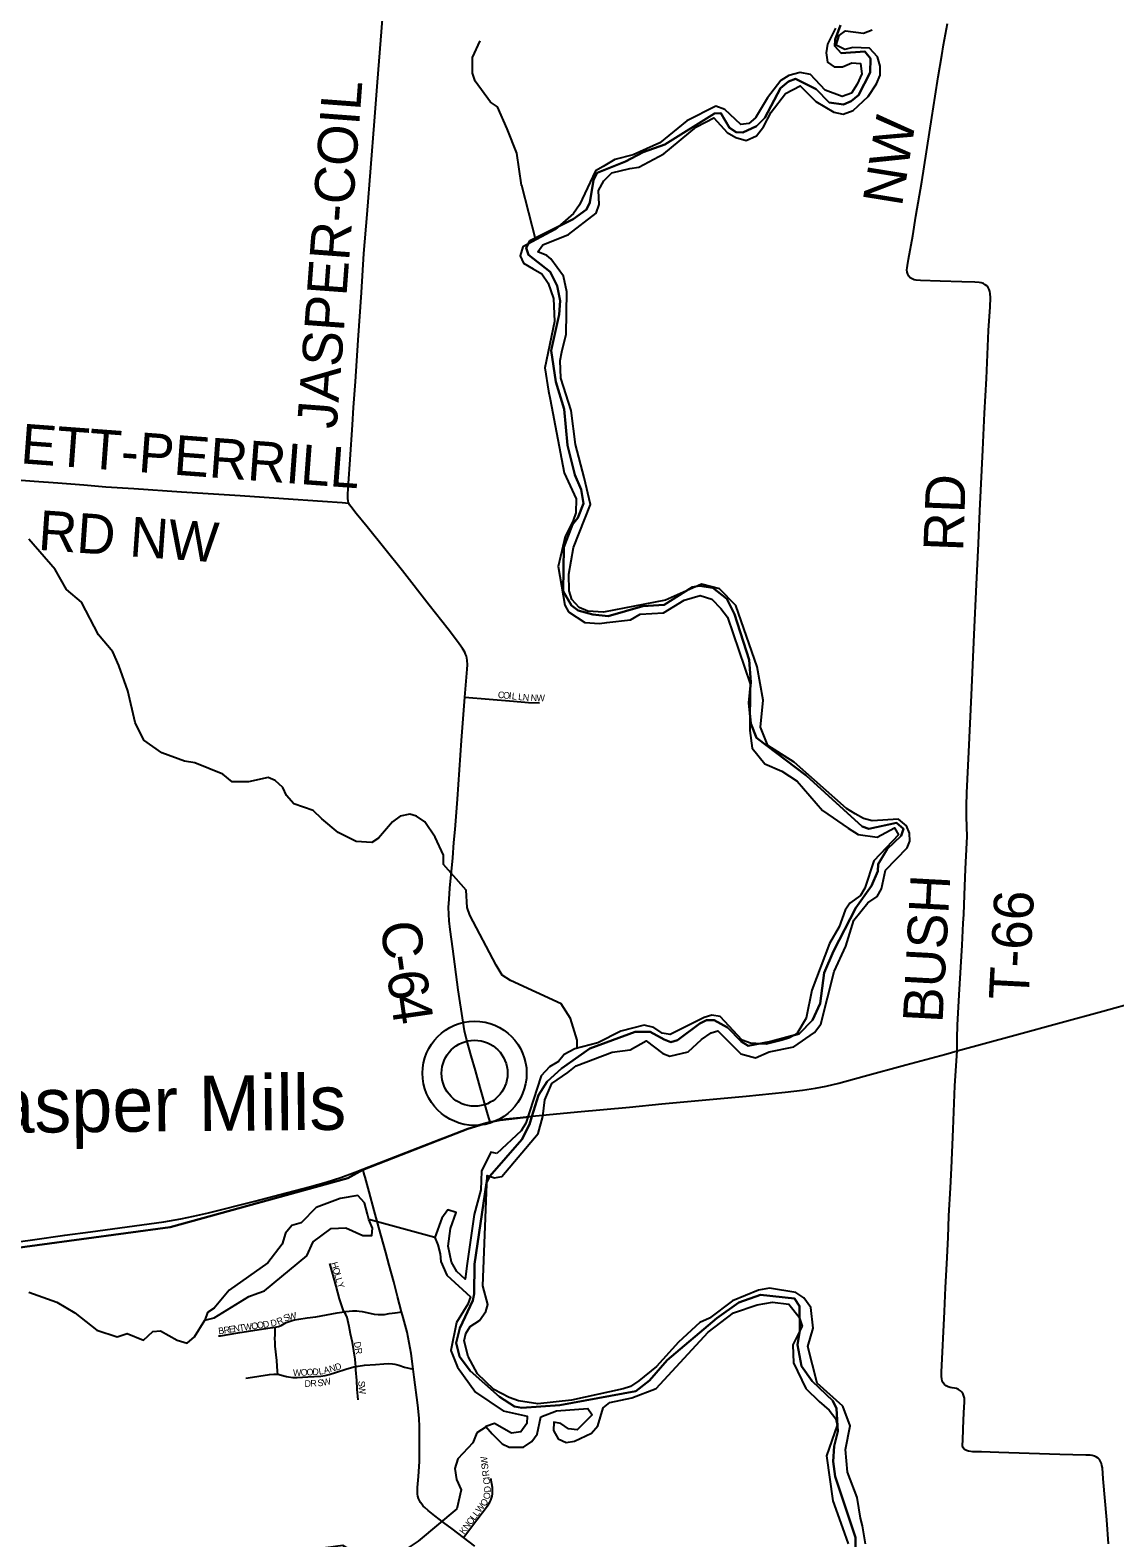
# Model space of a CAD drawing. Extents: x -51392 to 1635000, y 156707 to 696232.
# Drawn here: x 112561 to 120749, y 476810 to 488186 of the extents above; entities that cross this region are included whole.
import ezdxf

# ---------------------------------------------------------------- set-up
doc = ezdxf.new("R2010")
doc.units = 0
for name, color, linetype in [('GM_X_County_Road', 7, 'Continuous'), ('GM_X_County_Road_Text', 7, 'Continuous'), ('GM_X_Minor_Lake', 7, 'Continuous'), ('GM_X_Minor_River', 7, 'Continuous'), ('GM_X_Township', 7, 'Continuous'), ('GM_X_Township_Road', 7, 'Continuous'), ('GM_X_Township_Road_Text', 7, 'Continuous'), ('GM_X_Township_Subdivision', 7, 'Continuous'), ('GM_X_Township_Subdivision_Text', 7, 'Continuous'), ('GM_X_Unincorporated', 7, 'Continuous'), ('GM_X_Unincorporated_Text', 7, 'Continuous'), ('GM_X_US_Route', 7, 'Continuous')]:
    doc.layers.add(name, color=color, linetype=linetype)

msp = doc.modelspace()

# ---------------------------------------------------------------- linework, layer by layer
at = {"layer": 'GM_X_County_Road'}
for points in [[(114966, 484617), (114965, 484619), (114961, 484635), (114959, 484651), (114958, 484684), (114964, 484766), (114977, 484946), (114994, 485208), (115003, 485339), (115016, 485535), (115037, 485846), (115061, 486207), (115081, 486501), (115105, 486796), (115161, 487499), (115184, 487794), (115221, 488268)], [(112282, 484808), (112395, 484798), (112591, 484783), (112771, 484770), (112967, 484754), (113131, 484740), (113344, 484727), (113704, 484703), (114146, 484674), (114474, 484652), (114768, 484633), (114916, 484621), (114966, 484617)], [(115842, 483154), (115860, 483365), (115862, 483398), (115861, 483431), (115858, 483447), (115854, 483463), (115848, 483478), (115841, 483493), (115824, 483521), (115786, 483574), (115716, 483666), (115574, 483846), (115372, 484105), (115105, 484438), (115023, 484540), (114981, 484591), (114971, 484604), (114966, 484617)], [(116033, 479948), (116024, 479979), (116011, 480021), (115958, 480209), (115923, 480335), (115891, 480446), (115856, 480573), (115840, 480636), (115829, 480701), (115793, 480945), (115751, 481254), (115731, 481401), (115724, 481466), (115721, 481515), (115720, 481565), (115723, 481630), (115730, 481712), (115751, 481941), (115760, 482056), (115768, 482154), (115786, 482383), (115818, 482826), (115842, 483154)], [(115365, 478516), (115334, 478630), (115305, 478741), (115270, 478867), (115245, 478962), (115194, 479152), (115159, 479279), (115120, 479421), (115089, 479531), (115084, 479547), (115073, 479592)], [(115452, 478083), (115436, 478200), (115423, 478281), (115406, 478361), (115377, 478472), (115365, 478516)], [(115833, 476813), (115747, 476877), (115682, 476927), (115617, 476976), (115565, 477017), (115540, 477039), (115528, 477050), (115517, 477063), (115507, 477077), (115499, 477091), (115492, 477107), (115488, 477124), (115485, 477140), (115485, 477157), (115486, 477190), (115493, 477272), (115499, 477386), (115501, 477452), (115500, 477648), (115497, 477713), (115488, 477811), (115460, 478022), (115452, 478083)], [(115917, 476746), (115833, 476813)]]:
    msp.add_lwpolyline(points, dxfattribs=at)
at = {"layer": 'GM_X_Minor_Lake'}
for points in [[(115107, 479251), (115085, 479337), (115035, 479392), (114902, 479371), (114719, 479302), (114606, 479188), (114537, 479167), (114489, 479109), (114464, 479025), (114355, 478885), (114062, 478679), (113949, 478542), (113899, 478510), (113880, 478452), (113951, 478469), (114211, 478630), (114279, 478657), (114331, 478673), (114650, 478939), (114697, 479043), (114834, 479143), (114943, 479148), (115073, 479091), (115139, 479092), (115145, 479146), (115118, 479213)], [(115118, 479213), (115107, 479251)]]:
    msp.add_lwpolyline(points, dxfattribs=at)
at = {"layer": 'GM_X_Minor_River'}
for points in [[(118641, 488201), (118580, 488081), (118569, 488015), (118579, 487943), (118631, 487910), (118693, 487908), (118764, 487939), (118830, 487933), (118839, 487857), (118805, 487779), (118760, 487711), (118690, 487685), (118563, 487732), (118452, 487850), (118374, 487866), (118287, 487843), (118227, 487807), (118126, 487676), (118036, 487524), (117986, 487482), (117927, 487475), (117804, 487586), (117738, 487612), (117518, 487502), (117314, 487335), (117113, 487244), (116974, 487209), (116886, 487157), (116829, 487124), (116709, 486868), (116662, 486802), (116525, 486681), (116281, 486552), (116259, 486482), (116285, 486428), (116357, 486384), (116423, 486347), (116472, 486276), (116512, 486160), (116520, 485987), (116446, 485639), (116475, 485463), (116486, 485402), (116593, 484846), (116682, 484649), (116681, 484543), (116659, 484485), (116600, 484365), (116548, 484139), (116598, 483848), (116624, 483796), (116748, 483717), (116858, 483708), (116915, 483717), (117093, 483736), (117166, 483780), (117343, 483790), (117498, 483884), (117620, 483921), (117706, 483892), (117774, 483821), (117826, 483757), (117997, 483254), (117993, 482902), (118012, 482769), (118106, 482650), (118236, 482595), (118352, 482520), (118541, 482298), (118736, 482165), (118812, 482118), (118955, 482097), (119086, 482166), (119115, 482114), (118931, 481919), (118862, 481711), (118829, 481657), (118749, 481599), (118714, 481547)], [(117089, 487141), (117157, 487151), (117344, 487252), (117590, 487455), (117723, 487524), (117823, 487413), (117887, 487375), (117967, 487354), (118043, 487389), (118098, 487457), (118155, 487567), (118262, 487707), (118373, 487766), (118491, 487647), (118629, 487568), (118697, 487551), (118775, 487579), (118886, 487686), (118951, 487780), (118978, 487846), (118978, 487914), (118957, 487984), (118897, 488051), (118772, 488054), (118710, 488040), (118646, 488073), (118667, 488145), (118717, 488180), (118851, 488163), (118916, 488187)], [(116270, 487013), (116269, 487016), (116234, 487258), (116163, 487441), (116088, 487606), (116036, 487643), (115919, 487800), (115901, 487860), (115900, 487979), (115957, 488106)], [(116462, 486485), (116394, 486514), (116430, 486567), (116625, 486644), (116833, 486805), (116856, 486869), (116852, 486975), (116891, 487049), (116952, 487109), (117089, 487141)], [(116269, 487016), (116376, 486604)], [(118695, 477803), (118503, 477977), (118431, 478254), (118472, 478392), (118453, 478547), (118401, 478621), (118341, 478662), (118141, 478693), (118059, 478680), (117863, 478599), (117688, 478468), (117617, 478435), (117456, 478287), (117290, 478102), (117157, 477995), (117094, 477951), (117038, 477934), (116648, 477848), (116393, 477822), (116247, 477843), (116178, 477868), (116060, 477929), (115937, 478048), (115867, 478179), (115838, 478297), (115849, 478351), (115883, 478405), (115952, 478449), (116002, 478519), (116015, 478571), (115979, 478711), (116011, 479545), (116065, 479526), (116121, 479536), (116395, 479861), (116432, 479989), (116447, 480115), (116500, 480237), (116621, 480320), (116683, 480372), (116955, 480474), (117091, 480493), (117210, 480560), (117338, 480465), (117390, 480445), (117529, 480478), (117630, 480569), (117702, 480621), (117753, 480636), (117926, 480461), (118036, 480432), (118139, 480477), (118326, 480516), (118481, 480623), (118530, 480687), (118631, 481083), (118718, 481275), (118780, 481471), (118885, 481602), (118956, 481650), (118988, 481708), (119017, 481848), (119181, 482015), (119201, 482067), (119200, 482127), (119176, 482181), (119116, 482232), (118917, 482219), (118853, 482238), (118789, 482273), (118723, 482313), (118328, 482663), (118129, 482788), (118075, 482927), (118095, 483130), (118050, 483382), (117887, 483845), (117765, 483970), (117629, 484005), (117357, 483885), (116889, 483794), (116771, 483803), (116705, 483829), (116649, 483890), (116629, 483956), (116628, 484080), (116663, 484281), (116792, 484606), (116743, 484811), (116677, 485060), (116644, 485315), (116568, 485560), (116561, 485692), (116575, 485759), (116608, 485891), (116612, 486211), (116587, 486330), (116492, 486459), (116462, 486485)], [(116690, 480504), (116690, 480564), (116639, 480729), (116570, 480840), (116188, 481015), (116124, 481055), (116080, 481130), (115880, 481508), (115860, 481566), (115853, 481697), (115680, 481890), (115680, 481961), (115619, 482097), (115540, 482212), (115478, 482255), (115426, 482269), (115353, 482254), (115297, 482212), (115191, 482088), (115139, 482057), (115023, 482064), (114885, 482133), (114763, 482234), (114697, 482299), (114551, 482348), (114495, 482410), (114469, 482471), (114410, 482525), (114358, 482546), (114209, 482515), (114086, 482514), (114015, 482572), (113804, 482658), (113726, 482671), (113556, 482732), (113418, 482829), (113353, 482962), (113298, 483201), (113231, 483392), (113186, 483496), (113076, 483623), (112948, 483871), (112836, 483966), (112749, 484117), (112551, 484345)], [(118714, 481547), (118669, 481419), (118594, 481294), (118461, 480942), (118418, 480732), (118349, 480614), (118294, 480582), (118238, 480565), (118117, 480534), (117999, 480542), (117937, 480565), (117769, 480743), (117707, 480753), (117649, 480737), (117393, 480609), (117333, 480617), (117269, 480660), (117197, 480677), (117020, 480634), (116845, 480545), (116672, 480500), (116591, 480457), (116549, 480405), (116482, 480363), (116418, 480295), (116303, 479940), (116268, 479882), (116085, 479709)], [(116085, 479709), (116038, 479719), (115967, 479577), (115962, 479437), (115913, 479249), (115860, 478880), (115845, 478762), (115781, 478819), (115742, 478891), (115717, 479012), (115735, 479144), (115776, 479264), (115714, 479286), (115668, 479221), (115617, 479077), (115638, 479022), (115656, 478952), (115662, 478896), (115707, 478791), (115885, 478628), (115866, 478572), (115779, 478434), (115737, 478224), (115787, 478097), (115924, 477908), (116132, 477768), (116314, 477728), (116310, 477674), (116265, 477611), (116195, 477599), (116065, 477674), (116002, 477651), (116048, 477594), (116124, 477519), (116176, 477495), (116284, 477494), (116349, 477538), (116389, 477592), (116416, 477722), (116535, 477769), (116770, 477787), (116804, 477737), (116689, 477624), (116624, 477632), (116568, 477673), (116514, 477683), (116512, 477619), (116548, 477556), (116606, 477530), (116670, 477539), (116799, 477599), (116845, 477654), (116886, 477790), (116937, 477830), (117104, 477867), (117286, 477936)], [(115617, 479077), (115118, 479213)], [(112551, 478664), (112761, 478588), (112897, 478507), (113063, 478378), (113217, 478327), (113292, 478352), (113416, 478301), (113488, 478367), (113545, 478372), (113671, 478301), (113747, 478279), (113801, 478326), (113880, 478452)], [(117286, 477936), (117679, 478362), (117871, 478509), (118048, 478568), (118166, 478589), (118287, 478572), (118366, 478475), (118390, 478407), (118319, 478267), (118324, 478131), (118417, 477938), (118518, 477839), (118592, 477774), (118642, 477709), (118652, 477659), (118572, 477429), (118620, 477090), (118693, 476885), (118736, 476765)], [(118866, 476764), (118845, 476900), (118830, 476958), (118803, 477115), (118732, 477306), (118715, 477476), (118752, 477654), (118695, 477803)], [(116004, 477647), (115934, 477603), (115903, 477527), (115790, 477406), (115767, 477332), (115779, 477251), (115814, 477173), (115783, 477029), (115489, 476786), (115257, 476628), (115194, 476610), (115118, 476613), (115050, 476645), (114988, 476712), (114922, 476753), (114792, 476735), (114554, 476621), (114492, 476609), (114372, 476604), (114083, 476658), (113942, 476653), (113880, 476636), (113711, 476529), (113593, 476385)]]:
    msp.add_lwpolyline(points, dxfattribs=at)
at = {"layer": 'GM_X_Township'}
for points in [[(118679, 488224), (118637, 488115), (118636, 488065), (118684, 488011), (118861, 488025), (118904, 487971), (118901, 487867), (118814, 487696), (118758, 487649), (118702, 487624), (118593, 487639), (118494, 487741), (118339, 487818), (118285, 487797), (118225, 487749), (118106, 487523), (118043, 487460), (117940, 487413), (117890, 487415), (117840, 487448), (117776, 487560), (117726, 487556), (117353, 487324), (117188, 487266), (117056, 487195), (116840, 487109), (116813, 487054), (116786, 486886), (116760, 486833), (116659, 486760), (116333, 486595), (116305, 486543), (116324, 486491), (116487, 486362), (116539, 486256), (116562, 486144), (116555, 486040), (116495, 485768), (116529, 485532), (116593, 485326), (116618, 485054), (116672, 484830), (116721, 484720), (116738, 484614), (116695, 484507), (116655, 484455), (116590, 484286), (116585, 483953), (116647, 483845), (116697, 483807), (116808, 483776), (116925, 483763), (117187, 483840), (117346, 483849), (117559, 483983), (117614, 483992), (117714, 483977), (117819, 483895), (117877, 483778), (117988, 483434), (118000, 483265), (117987, 483111), (118001, 482955), (118044, 482845), (118420, 482561), (118841, 482178), (118892, 482160), (119102, 482204), (119153, 482159), (119137, 482106), (119030, 482005), (118962, 481894), (118959, 481840), (118912, 481730), (118795, 481564), (118625, 481236), (118556, 481073), (118524, 480842), (118467, 480715), (118367, 480614), (118153, 480556), (117982, 480522), (117928, 480556), (117826, 480661), (117725, 480717), (117667, 480716), (117615, 480692), (117447, 480564), (117397, 480549), (117347, 480569), (117242, 480628), (117127, 480629), (116785, 480502), (116571, 480352), (116464, 480254), (116398, 480150), (116349, 479989), (116109, 479962), (116020, 479943), (115865, 479896), (115639, 479808), (115073, 479587), (114959, 479523), (113617, 479154), (111943, 478929)], [(118788, 476636), (118791, 476812), (118638, 477272), (118623, 477386), (118630, 477501), (118659, 477613), (118648, 477785), (118621, 477843), (118465, 477992), (118384, 478106), (118354, 478266), (118371, 478375), (118369, 478559), (118331, 478615), (118075, 478643), (117911, 478585), (117745, 478467), (117369, 478151), (117237, 477998), (117134, 477917), (116560, 477811), (116273, 477791), (116217, 477800), (116103, 477875), (115883, 478070), (115801, 478178), (115778, 478282), (115804, 478392), (115902, 478601), (115912, 478652), (115914, 478876), (116005, 479489), (116032, 479539), (116273, 479816), (116330, 479928), (116349, 479989), (116398, 480150), (116464, 480254), (116571, 480352), (116785, 480502), (117127, 480629), (117242, 480628), (117347, 480569), (117397, 480549), (117447, 480564), (117615, 480692), (117667, 480716), (117725, 480717), (117826, 480661), (117928, 480556), (117982, 480522), (118153, 480556), (118367, 480614), (118467, 480715), (118524, 480842), (118556, 481073), (118625, 481236), (118795, 481564), (118912, 481730), (118959, 481840), (118962, 481894), (119030, 482005), (119137, 482106), (119153, 482159), (119102, 482204), (118892, 482160), (118841, 482178), (118420, 482561), (118044, 482845), (118001, 482955), (117987, 483111), (118000, 483265), (117988, 483434), (117877, 483778), (117819, 483895), (117714, 483977), (117614, 483992), (117559, 483983), (117346, 483849), (117187, 483840), (116925, 483763), (116808, 483776), (116697, 483807), (116647, 483845), (116585, 483953), (116590, 484286), (116655, 484455), (116695, 484507), (116738, 484614), (116721, 484720), (116672, 484830), (116618, 485054), (116593, 485326), (116529, 485532), (116495, 485768), (116555, 486040), (116562, 486144), (116539, 486256), (116487, 486362), (116324, 486491), (116305, 486543), (116333, 486595), (116659, 486760), (116760, 486833), (116786, 486886), (116813, 487054), (116840, 487109), (117056, 487195), (117188, 487266), (117353, 487324), (117726, 487556), (117776, 487560), (117840, 487448), (117890, 487415), (117940, 487413), (118043, 487460), (118106, 487523), (118225, 487749), (118285, 487797), (118339, 487818), (118494, 487741), (118593, 487639), (118702, 487624), (118758, 487649), (118814, 487696), (118901, 487867), (118904, 487971), (118861, 488025), (118684, 488011), (118636, 488065), (118637, 488115), (118679, 488224)], [(111943, 478929), (113617, 479154), (114959, 479523), (115073, 479587), (115639, 479808), (115865, 479896), (116020, 479943), (116109, 479962), (116349, 479989), (116330, 479928), (116273, 479816), (116032, 479539), (116005, 479489), (115914, 478876), (115912, 478652), (115902, 478601), (115804, 478392), (115778, 478282), (115801, 478178), (115883, 478070), (116103, 477875), (116217, 477800), (116273, 477791), (116560, 477811), (117134, 477917), (117237, 477998), (117369, 478151), (117745, 478467), (117911, 478585), (118075, 478643), (118331, 478615), (118369, 478559), (118371, 478375), (118354, 478266), (118384, 478106), (118465, 477992), (118621, 477843), (118648, 477785), (118659, 477613), (118630, 477501), (118623, 477386), (118638, 477272), (118791, 476812), (118788, 476636)]]:
    msp.add_lwpolyline(points, dxfattribs=at)
at = {"layer": 'GM_X_Township_Road'}
for points in [[(119559, 480484), (119559, 480527), (119560, 480579), (119562, 480678), (119575, 480907), (119596, 481283), (119605, 481447), (119608, 481513), (119614, 481660), (119623, 481857), (119633, 482053), (119634, 482102), (119629, 482250), (119629, 482332), (119633, 482430), (119647, 482741), (119667, 483167), (119688, 483626), (119706, 484002), (119720, 484313), (119731, 484559), (119752, 485018), (119766, 485296), (119780, 485558), (119796, 485919), (119807, 486099), (119810, 486165), (119809, 486198), (119806, 486214), (119801, 486229), (119794, 486243), (119784, 486256), (119771, 486265), (119757, 486273), (119741, 486278), (119726, 486282), (119693, 486285), (119594, 486287), (119430, 486291), (119282, 486296), (119249, 486299), (119233, 486303), (119219, 486310), (119205, 486318), (119194, 486330), (119187, 486344), (119182, 486360), (119180, 486376), (119181, 486393), (119183, 486409), (119191, 486458), (119223, 486635), (119248, 486781), (119291, 487040), (119367, 487526), (119393, 487688), (119415, 487833), (119442, 487995), (119456, 488076), (119486, 488237)], [(120700, 476766), (120688, 476946), (120661, 477256), (120655, 477339), (120652, 477355), (120648, 477371), (120642, 477386), (120634, 477400), (120623, 477411), (120610, 477420), (120595, 477427), (120579, 477431), (120563, 477433), (120530, 477435), (120431, 477436), (120333, 477439), (120103, 477446), (119874, 477453), (119743, 477458), (119677, 477460), (119645, 477464), (119629, 477469), (119615, 477476), (119604, 477488), (119600, 477504), (119601, 477553), (119607, 477700), (119612, 477799), (119614, 477832), (119614, 477848), (119613, 477864), (119610, 477880), (119604, 477895), (119595, 477909), (119583, 477920), (119569, 477929), (119554, 477936), (119538, 477939), (119522, 477941), (119506, 477945), (119490, 477950), (119476, 477957), (119463, 477967), (119453, 477980), (119446, 477995), (119442, 478010), (119440, 478027), (119440, 478059), (119464, 478518), (119472, 478698), (119480, 478878), (119490, 479075), (119497, 479239), (119508, 479452), (119515, 479599), (119528, 479894), (119542, 480221), (119559, 480484)]]:
    msp.add_lwpolyline(points, dxfattribs=at)
at = {"layer": 'GM_X_Township_Subdivision'}
for points in [[(115842, 483154), (116209, 483123), (116324, 483114), (116406, 483111)], [(114931, 478515), (114926, 478523), (114896, 478614), (114871, 478708), (114823, 478880)], [(114410, 478399), (114436, 478404), (114455, 478412), (114494, 478434), (114509, 478441), (114540, 478451), (114556, 478455), (114588, 478461), (114652, 478469), (114717, 478478), (114879, 478507), (114931, 478515)], [(114931, 478515), (114944, 478517), (114995, 478522), (115027, 478522), (115045, 478521), (115068, 478518), (115124, 478505), (115157, 478498), (115189, 478494), (115237, 478496), (115271, 478502), (115317, 478509), (115334, 478511), (115365, 478516)], [(115019, 478103), (115018, 478126), (115014, 478158), (114993, 478284), (114980, 478349), (114969, 478404), (114953, 478472), (114943, 478496), (114931, 478515)], [(113982, 478333), (113998, 478335), (114128, 478357), (114209, 478370), (114354, 478392), (114410, 478399)], [(114431, 478044), (114429, 478064), (114422, 478148), (114411, 478256), (114410, 478285), (114409, 478315), (114411, 478343), (114411, 478373), (114410, 478399)], [(115019, 478103), (115037, 478106), (115086, 478113), (115167, 478117), (115232, 478123), (115265, 478125), (115297, 478123), (115313, 478120), (115345, 478112), (115386, 478099), (115419, 478090), (115452, 478083)], [(114190, 478015), (114206, 478017), (114287, 478029), (114367, 478042), (114400, 478045), (114416, 478045), (114431, 478044)], [(114431, 478044), (114432, 478044), (114448, 478041), (114495, 478028), (114511, 478024), (114544, 478021), (114576, 478021), (114658, 478025), (114755, 478030), (114787, 478035), (114819, 478043), (114865, 478058), (114943, 478083), (115005, 478101), (115019, 478103)], [(115037, 477851), (115030, 477933), (115026, 477997), (115020, 478077), (115019, 478103)], [(115833, 476813), (115934, 476945), (116013, 477051), (116031, 477079), (116038, 477094), (116044, 477109), (116048, 477125), (116051, 477142), (116052, 477158), (116051, 477175), (116050, 477191), (116039, 477257)]]:
    msp.add_lwpolyline(points, dxfattribs=at)
at = {"layer": 'GM_X_Unincorporated'}
for radius in [393, 249]:
    msp.add_circle((115916, 480315), radius, dxfattribs=at)
at = {"layer": 'GM_X_US_Route'}
msp.add_lwpolyline([(112269, 479017), (112578, 479059), (112822, 479093), (113017, 479119), (113569, 479195), (113699, 479217), (113795, 479236), (113907, 479263), (114257, 479351), (114495, 479412), (114670, 479459), (114796, 479494), (114905, 479530), (115014, 479569), (115073, 479592), (115274, 479670), (115656, 479818), (115871, 479898), (115948, 479925), (116011, 479943), (116033, 479948), (116059, 479955), (116107, 479964), (116155, 479971), (116285, 479985), (116351, 479992), (116694, 480025), (117086, 480060), (117330, 480084), (117690, 480118), (117967, 480143), (118261, 480173), (118392, 480188), (118489, 480202), (118570, 480218), (118666, 480241), (118856, 480293), (119172, 480378), (119473, 480460), (119559, 480484), (119995, 480604), (120343, 480698), (120659, 480785), (120912, 480855)], dxfattribs=at)

# ---------------------------------------------------------------- texts
at = {"layer": 'GM_X_County_Road_Text'}
for s, rotation, p in [('JASPER-COIL', 85.7475, (114874, 485173)), ('BURNETT-PERRILL', 355.7645, (111349, 485002)), ('RD NW', 355.9628, (112616, 484265)), ('C', 276.5602, (115206, 481449)), ('-', 277.9875, (115235, 481196)), ('6', 278.1506, (115252, 481073)), ('4', 278.2165, (115279, 480890))]:
    msp.add_text(s, height=300, rotation=rotation, dxfattribs=at).set_placement(p)
at = {"layer": 'GM_X_Township_Road_Text'}
for s, rotation, p in [('NW', 80.8117, (119141, 486848)), ('RD', 87.8116, (119603, 484250)), ('BUSH', 86.9442, (119448, 480691)), ('T-66', 87.0049, (120097, 480863))]:
    msp.add_text(s, height=300, rotation=rotation, dxfattribs=at).set_placement(p)
at = {"layer": 'GM_X_Township_Subdivision_Text'}
for s, rotation, p in [('C', 354.0884, (116090, 483148)), ('O', 354.1094, (116129, 483144)), ('I', 354.1218, (116173, 483140)), ('L', 354.1048, (116195, 483137)), ('L', 354.1048, (116243, 483132)), ('N', 354.7414, (116278, 483129)), ('N', 358.4034, (116339, 483124)), ('W', 358.6411, (116383, 483123)), ('H', 286.3669, (114831, 478883)), ('O', 286.3458, (114843, 478841)), ('L', 286.3545, (114856, 478799)), ('L', 286.3791, (114865, 478765)), ('Y', 287.6198, (114876, 478730)), ('R', 24.4311, (114435, 478415)), ('S', 23.4106, (114485, 478439)), ('W', 13.1841, (114515, 478452)), ('B', 8.2359, (113985, 478345)), ('R', 8.2507, (114025, 478351)), ('E', 8.2505, (114064, 478357)), ('N', 8.2503, (114099, 478362)), ('T', 8.2755, (114142, 478368)), ('W', 8.2454, (114177, 478373)), ('O', 8.2328, (114234, 478381)), ('O', 8.2328, (114277, 478388)), ('D', 8.2411, (114321, 478394)), ('D', 10.6702, (114380, 478403)), ('DR', 279.9969, (115004, 478286)), ('N', 15.2557, (114826, 478058)), ('D', 18.524, (114871, 478071)), ('W', 359.9333, (114545, 478032)), ('O', 3.4404, (114605, 478032)), ('O', 3.4404, (114649, 478034)), ('D', 3.6666, (114693, 478037)), ('S', 4.6068, (114732, 477953)), ('L', 10.1072, (114743, 478040)), ('W', 11.9938, (114774, 477957)), ('A', 14.0156, (114782, 478047)), ('D', 1.6096, (114633, 477949)), ('R', 3.0497, (114678, 477950)), ('S', 271.9044, (115038, 477994)), ('W', 277.6497, (115039, 477953)), ('W', 97.0094, (116017, 477364)), ('S', 96.9994, (116021, 477329)), ('R', 96.9974, (116027, 477277)), ('I', 96.9808, (116030, 477255)), ('C', 96.6213, (116035, 477215)), ('O', 55.1148, (115994, 477042)), ('O', 76.7433, (116027, 477097)), ('D', 92.5598, (116039, 477154)), ('L', 53.1715, (115937, 476966)), ('W', 53.1727, (115958, 476995)), ('K', 53.1791, (115837, 476832)), ('N', 53.1726, (115863, 476868)), ('O', 53.1965, (115890, 476903)), ('L', 53.1715, (115916, 476938))]:
    msp.add_text(s, height=50, rotation=rotation, dxfattribs=at).set_placement(p)
at = {"layer": 'GM_X_Unincorporated_Text'}
msp.add_text('Jasper Mills', height=417, rotation=0.5386, dxfattribs=at).set_placement((112005, 479862))

doc.saveas('drawing.dxf')
